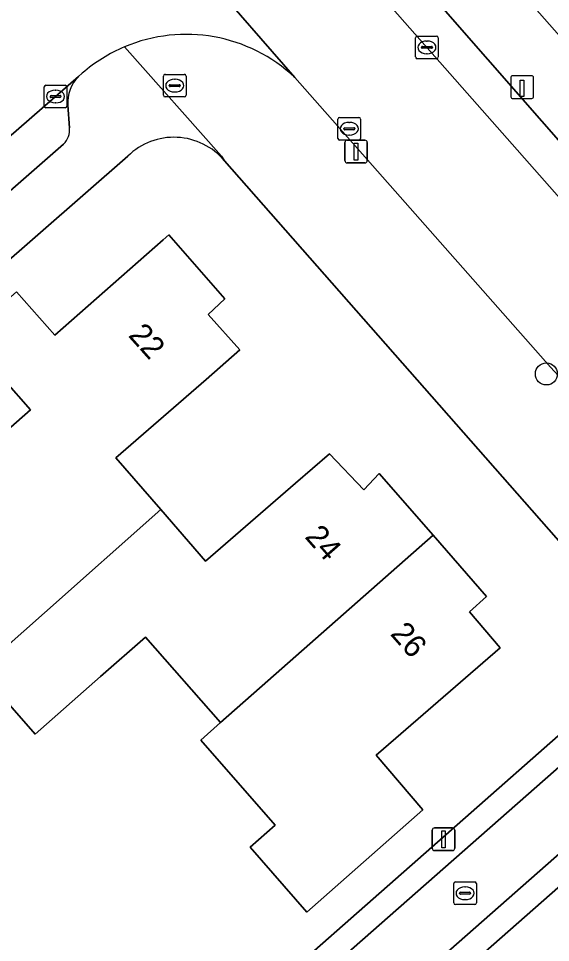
# Model space of a CAD drawing. Extents: x 157320 to 158835, y 386650 to 388491.
# Drawn here: x 157647.93 to 157671.43, y 387796.62 to 387837.43 of the extents above; entities that cross this region are included whole.
import ezdxf

# ---------------------------------------------------------------- set-up
doc = ezdxf.new("R2010")
doc.units = 0
for name, color, linetype in [('IMGEO_Boom', 7, 'Continuous'), ('IMGEO_Brandkraan', 7, 'Continuous'), ('IMGEO_Erf', 7, 'Continuous'), ('IMGEO_Kolk', 7, 'Continuous'), ('IMGEO_Laadpaal', 7, 'Continuous'), ('IMGEO_Lichtmast', 7, 'Continuous'), ('IMGEO_Muur', 7, 'Continuous'), ('IMGEO_Pand', 7, 'Continuous'), ('IMGEO_Pand_nummerreeks', 7, 'Continuous'), ('IMGEO_Parkeervlak_open', 7, 'Continuous'), ('IMGEO_Rijbaan_lokaal_open', 7, 'Continuous'), ('IMGEO_Voetpad_open', 7, 'Continuous')]:
    doc.layers.add(name, color=color, linetype=linetype)

msp = doc.modelspace()

# ---------------------------------------------------------------- linework, layer by layer
at = {"layer": 'IMGEO_Boom'}
msp.add_circle((157671.251, 387821.734), 0.489, dxfattribs=at)
at = {"layer": 'IMGEO_Brandkraan'}
for p, q in [((157654.334, 387834.039), (157654.334, 387834.891)), ((157654.409, 387834.965), (157655.261, 387834.965)), ((157654.822, 387834.745), (157654.847, 387834.745)), ((157655.335, 387834.891), (157655.335, 387834.039)), ((157654.593, 387834.459), (157654.593, 387834.471)), ((157655.031, 387834.422), (157654.633, 387834.422)), ((157654.636, 387834.508), (157655.034, 387834.508)), ((157655.077, 387834.471), (157655.077, 387834.459)), ((157655.261, 387833.965), (157654.409, 387833.965)), ((157654.845, 387834.185), (157654.82, 387834.185))]:
    msp.add_line(p, q, dxfattribs=at)
for points in [[(157654.334, 387834.039), (157654.334, 387834.891)], [(157654.409, 387834.965), (157655.261, 387834.965)], [(157655.335, 387834.891), (157655.335, 387834.039)], [(157655.261, 387833.965), (157654.409, 387833.965)]]:
    msp.add_lwpolyline(points, dxfattribs=at)
for centre, radius, start, end in [((157654.411, 387834.889), 0.0765, 91.552, 178.448), ((157654.411, 387834.889), 0.0765, 91.552, 178.448), ((157655.259, 387834.889), 0.0765, 1.552, 88.448), ((157655.259, 387834.889), 0.0765, 1.552, 88.448), ((157654.633, 387834.468), 0.0403, 85.8775, 175.7526), ((157654.63, 387834.458), 0.0366, 178.938, 274.7102), ((157655.034, 387834.465), 0.043, 264.8664, 352.4533), ((157655.038, 387834.47), 0.0386, 1.7309, 96.639), ((157654.411, 387834.041), 0.0765, 181.552, 268.448), ((157654.411, 387834.041), 0.0765, 181.552, 268.448), ((157655.259, 387834.041), 0.0765, 271.552, 358.448), ((157655.259, 387834.041), 0.0765, 271.552, 358.448)]:
    msp.add_arc(centre, radius, start, end, dxfattribs=at)
for centre, major_axis, ratio, start_param, end_param in [((157654.821, 387834.465), (-0.387, 0.002), 0.722429, 4.712389, 7.853982), ((157654.846, 387834.465), (-0.39, 0.002), 0.717154, 1.570796, 4.712389)]:
    msp.add_ellipse(centre, major_axis=major_axis, ratio=ratio, start_param=start_param, end_param=end_param, dxfattribs=at)
at = {"layer": 'IMGEO_Erf'}
for points in [[(157611.28, 387905.251), (157676.491, 387831.375), (157676.979, 387830.83), (157677.515, 387830.331), (157678.092, 387829.881), (157678.708, 387829.485), (157679.356, 387829.145), (157680.033, 387828.865), (157680.731, 387828.646), (157681.446, 387828.491), (157682.173, 387828.4), (157682.904, 387828.374), (157683.635, 387828.414), (157684.359, 387828.519), (157684.789, 387828.613), (157729.457, 387839.094), (157721.261, 387874.483)], [(157652.762, 387831.358), (157646.906, 387826.236), (157630.79, 387812.141), (157631.345, 387811.51), (157633.511, 387813.414), (157635.08, 387811.629), (157632.915, 387809.725), (157637.888, 387804.07), (157635.493, 387801.964), (157628.395, 387810.035), (157617.003, 387800.065), (157607.442, 387791.699)], [(157674.457, 387811.128), (157674.052, 387811.797), (157657.033, 387831.146)], [(157647.848, 387825.356), (157649.533, 387823.44), (157654.324, 387827.656), (157654.571, 387827.873), (157657.051, 387825.051), (157656.306, 387824.359), (157657.71, 387822.791), (157656.215, 387821.493), (157652.227, 387818.03), (157654.216, 387815.74), (157656.197, 387813.459), (157660.171, 387816.909), (157661.666, 387818.207), (157663.182, 387816.62), (157663.86, 387817.336), (157666.242, 387814.61), (157668.61, 387811.9), (157667.854, 387811.224), (157669.212, 387809.637), (157667.682, 387808.313), (157664.606, 387805.65), (157663.725, 387804.887), (157665.79, 387802.474), (157660.67, 387797.962), (157658.159, 387800.823), (157659.275, 387801.802), (157655.982, 387805.556), (157656.857, 387806.329), (157653.545, 387810.104), (157651.561, 387808.362), (157648.667, 387805.82), (157646.197, 387808.634)], [(157732.841, 387824.842), (157689.538, 387814.686), (157654.452, 387783.817), (157657.034, 387778.861), (157661.114, 387762.545), (157664.445, 387758.077), (157662.927, 387756.946), (157668.103, 387750), (157672.52, 387744.072), (157667.404, 387740.347), (157668.545, 387738.825), (157675.463, 387729.915), (157675.349, 387729.779), (157690.547, 387709.406)], [(157644.367, 387816.559), (157648.46, 387820.15), (157647.298, 387821.475)], [(157665.567, 387800.286), (157674.127, 387807.828), (157674.136, 387807.943)], [(157650.531, 387787.038), (157665.567, 387800.286)]]:
    msp.add_lwpolyline(points, dxfattribs=at)
msp.add_arc((157654.799, 387829.268), 2.918, 40.0468, 134.2699, dxfattribs=at)
at = {"layer": 'IMGEO_Kolk'}
for p, q in [((157665.471, 387835.731), (157665.471, 387836.583)), ((157665.546, 387836.657), (157666.398, 387836.657)), ((157665.959, 387836.437), (157665.984, 387836.437)), ((157666.472, 387836.583), (157666.472, 387835.731)), ((157665.73, 387836.151), (157665.73, 387836.163)), ((157666.168, 387836.114), (157665.77, 387836.114)), ((157665.773, 387836.2), (157666.171, 387836.2)), ((157666.214, 387836.163), (157666.214, 387836.151)), ((157666.398, 387835.657), (157665.546, 387835.657)), ((157665.982, 387835.877), (157665.957, 387835.877)), ((157649.068, 387833.56), (157649.068, 387834.412)), ((157649.143, 387834.486), (157649.995, 387834.486)), ((157650.069, 387834.412), (157650.069, 387833.56)), ((157649.327, 387833.98), (157649.327, 387833.992)), ((157649.765, 387833.943), (157649.367, 387833.943)), ((157649.37, 387834.029), (157649.768, 387834.029)), ((157649.556, 387834.266), (157649.581, 387834.266)), ((157649.811, 387833.992), (157649.811, 387833.98)), ((157649.995, 387833.486), (157649.143, 387833.486)), ((157649.579, 387833.706), (157649.554, 387833.706)), ((157662.117, 387833.061), (157662.969, 387833.061)), ((157662.042, 387832.135), (157662.042, 387832.987)), ((157662.53, 387832.841), (157662.555, 387832.841)), ((157663.043, 387832.987), (157663.043, 387832.135)), ((157662.301, 387832.555), (157662.301, 387832.567)), ((157662.739, 387832.518), (157662.341, 387832.518)), ((157662.344, 387832.604), (157662.742, 387832.604)), ((157662.553, 387832.281), (157662.528, 387832.281)), ((157662.785, 387832.567), (157662.785, 387832.555)), ((157662.969, 387832.061), (157662.117, 387832.061)), ((157667.157, 387798.369), (157667.157, 387799.221)), ((157667.232, 387799.295), (157668.084, 387799.295)), ((157668.158, 387799.221), (157668.158, 387798.369)), ((157667.416, 387798.789), (157667.416, 387798.801)), ((157667.459, 387798.838), (157667.857, 387798.838)), ((157667.645, 387799.075), (157667.67, 387799.075)), ((157667.9, 387798.801), (157667.9, 387798.789)), ((157667.854, 387798.752), (157667.456, 387798.752)), ((157667.668, 387798.515), (157667.643, 387798.515)), ((157668.084, 387798.295), (157667.232, 387798.295))]:
    msp.add_line(p, q, dxfattribs=at)
for points in [[(157665.471, 387835.731), (157665.471, 387836.583)], [(157665.546, 387836.657), (157666.398, 387836.657)], [(157666.472, 387836.583), (157666.472, 387835.731)], [(157666.398, 387835.657), (157665.546, 387835.657)], [(157649.068, 387833.56), (157649.068, 387834.412)], [(157649.143, 387834.486), (157649.995, 387834.486)], [(157650.069, 387834.412), (157650.069, 387833.56)], [(157649.995, 387833.486), (157649.143, 387833.486)], [(157662.117, 387833.061), (157662.969, 387833.061)], [(157662.042, 387832.135), (157662.042, 387832.987)], [(157663.043, 387832.987), (157663.043, 387832.135)], [(157662.969, 387832.061), (157662.117, 387832.061)], [(157667.157, 387798.369), (157667.157, 387799.221)], [(157667.232, 387799.295), (157668.084, 387799.295)], [(157668.158, 387799.221), (157668.158, 387798.369)], [(157668.084, 387798.295), (157667.232, 387798.295)]]:
    msp.add_lwpolyline(points, dxfattribs=at)
for centre, radius, start, end in [((157665.548, 387836.581), 0.0765, 91.552, 178.448), ((157665.548, 387836.581), 0.0765, 91.552, 178.448), ((157666.396, 387836.581), 0.0765, 1.552, 88.448), ((157666.396, 387836.581), 0.0765, 1.552, 88.448), ((157665.77, 387836.16), 0.0403, 85.8775, 175.7526), ((157665.767, 387836.15), 0.0366, 178.938, 274.7102), ((157666.171, 387836.157), 0.043, 264.8664, 352.4533), ((157666.175, 387836.162), 0.0386, 1.7309, 96.639), ((157665.548, 387835.733), 0.0765, 181.552, 268.448), ((157665.548, 387835.733), 0.0765, 181.552, 268.448), ((157666.396, 387835.733), 0.0765, 271.552, 358.448), ((157666.396, 387835.733), 0.0765, 271.552, 358.448), ((157649.145, 387834.41), 0.0765, 91.552, 178.448), ((157649.145, 387834.41), 0.0765, 91.552, 178.448), ((157649.993, 387834.41), 0.0765, 1.552, 88.448), ((157649.993, 387834.41), 0.0765, 1.552, 88.448), ((157649.367, 387833.989), 0.0403, 85.8775, 175.7526), ((157649.364, 387833.979), 0.0366, 178.938, 274.7102), ((157649.768, 387833.986), 0.043, 264.8664, 352.4533), ((157649.772, 387833.991), 0.0386, 1.7309, 96.639), ((157649.145, 387833.562), 0.0765, 181.552, 268.448), ((157649.145, 387833.562), 0.0765, 181.552, 268.448), ((157649.993, 387833.562), 0.0765, 271.552, 358.448), ((157649.993, 387833.562), 0.0765, 271.552, 358.448), ((157662.119, 387832.985), 0.0765, 91.552, 178.448), ((157662.119, 387832.985), 0.0765, 91.552, 178.448), ((157662.967, 387832.985), 0.0765, 1.552, 88.448), ((157662.967, 387832.985), 0.0765, 1.552, 88.448), ((157662.341, 387832.564), 0.0403, 85.8775, 175.7526), ((157662.338, 387832.554), 0.0366, 178.938, 274.7102), ((157662.742, 387832.561), 0.043, 264.8664, 352.4533), ((157662.746, 387832.566), 0.0386, 1.7309, 96.639), ((157662.119, 387832.137), 0.0765, 181.552, 268.448), ((157662.119, 387832.137), 0.0765, 181.552, 268.448), ((157662.967, 387832.137), 0.0765, 271.552, 358.448), ((157662.967, 387832.137), 0.0765, 271.552, 358.448), ((157667.234, 387799.219), 0.0765, 91.552, 178.448), ((157667.234, 387799.219), 0.0765, 91.552, 178.448), ((157668.082, 387799.219), 0.0765, 1.552, 88.448), ((157668.082, 387799.219), 0.0765, 1.552, 88.448), ((157667.456, 387798.798), 0.0403, 85.8775, 175.7526), ((157667.453, 387798.788), 0.0366, 178.938, 274.7102), ((157667.857, 387798.795), 0.043, 264.8664, 352.4533), ((157667.861, 387798.8), 0.0386, 1.7309, 96.639), ((157667.234, 387798.371), 0.0765, 181.552, 268.448), ((157667.234, 387798.371), 0.0765, 181.552, 268.448), ((157668.082, 387798.371), 0.0765, 271.552, 358.448), ((157668.082, 387798.371), 0.0765, 271.552, 358.448)]:
    msp.add_arc(centre, radius, start, end, dxfattribs=at)
for centre, major_axis, ratio, start_param, end_param in [((157665.958, 387836.157), (-0.387, 0.002), 0.722429, 4.712389, 7.853982), ((157665.983, 387836.157), (-0.39, 0.002), 0.717154, 1.570796, 4.712389), ((157649.555, 387833.986), (-0.387, 0.002), 0.722429, 4.712389, 7.853982), ((157649.58, 387833.986), (-0.39, 0.002), 0.717154, 1.570796, 4.712389), ((157662.529, 387832.561), (-0.387, 0.002), 0.722429, 4.712389, 7.853982), ((157662.554, 387832.561), (-0.39, 0.002), 0.717154, 1.570796, 4.712389), ((157667.644, 387798.795), (-0.387, 0.002), 0.722429, 4.712389, 7.853982), ((157667.669, 387798.795), (-0.39, 0.002), 0.717154, 1.570796, 4.712389)]:
    msp.add_ellipse(centre, major_axis=major_axis, ratio=ratio, start_param=start_param, end_param=end_param, dxfattribs=at)
at = {"layer": 'IMGEO_Laadpaal'}
for p, q in [((157669.68, 387834.816), (157669.68, 387833.975)), ((157669.68, 387834.816), (157669.68, 387833.975)), ((157670.596, 387834.9), (157669.755, 387834.9)), ((157670.596, 387834.9), (157669.755, 387834.9)), ((157670.68, 387833.984), (157670.68, 387834.825)), ((157670.68, 387833.984), (157670.68, 387834.825)), ((157669.764, 387833.9), (157670.605, 387833.9)), ((157669.764, 387833.9), (157670.605, 387833.9))]:
    msp.add_line(p, q, dxfattribs=at)
msp.add_lwpolyline([(157670.095, 387834.713), (157670.255, 387834.713), (157670.255, 387833.98), (157670.095, 387833.98), (157670.095, 387834.713)], dxfattribs=at)
for centre, start, end in [((157669.758, 387834.822), 92.4484, 184.2845), ((157669.758, 387834.822), 92.4484, 184.2845), ((157670.602, 387834.822), 2.4484, 94.2845), ((157670.602, 387834.822), 2.4484, 94.2845), ((157669.758, 387833.978), 182.4484, 274.2845), ((157669.758, 387833.978), 182.4484, 274.2845), ((157670.602, 387833.978), 272.4484, 4.2845), ((157670.602, 387833.978), 272.4484, 4.2845)]:
    msp.add_arc(centre, 0.0779, start, end, dxfattribs=at)
at = {"layer": 'IMGEO_Lichtmast'}
for p, q in [((157662.346, 387831.155), (157662.346, 387831.955)), ((157662.346, 387831.955), (157662.346, 387831.155)), ((157662.446, 387832.055), (157663.236, 387832.055)), ((157663.236, 387832.055), (157662.446, 387832.055)), ((157663.336, 387831.955), (157663.336, 387831.155)), ((157663.336, 387831.155), (157663.336, 387831.955)), ((157663.236, 387831.055), (157662.446, 387831.055)), ((157662.446, 387831.055), (157663.236, 387831.055)), ((157666.311, 387801.682), (157667.101, 387801.682)), ((157667.101, 387801.682), (157666.311, 387801.682)), ((157666.211, 387800.782), (157666.211, 387801.582)), ((157666.211, 387801.582), (157666.211, 387800.782)), ((157667.201, 387801.582), (157667.201, 387800.782)), ((157667.201, 387800.782), (157667.201, 387801.582)), ((157667.101, 387800.682), (157666.311, 387800.682)), ((157666.311, 387800.682), (157667.101, 387800.682))]:
    msp.add_line(p, q, dxfattribs=at)
for points in [[(157662.766, 387831.93), (157662.916, 387831.93), (157662.916, 387831.18), (157662.766, 387831.18), (157662.766, 387831.93)], [(157666.631, 387801.557), (157666.781, 387801.557), (157666.781, 387800.807), (157666.631, 387800.807), (157666.631, 387801.557)]]:
    msp.add_lwpolyline(points, dxfattribs=at)
for centre, start, end in [((157662.446, 387831.955), 90, 180), ((157662.446, 387831.955), 90, 180), ((157663.236, 387831.955), 0, 90), ((157663.236, 387831.955), 360, 90), ((157662.446, 387831.155), 180, 270), ((157662.446, 387831.155), 180, 270), ((157663.236, 387831.155), 270, 0), ((157663.236, 387831.155), 270, 0), ((157666.311, 387801.582), 90, 180), ((157666.311, 387801.582), 90, 180), ((157667.101, 387801.582), 0, 90), ((157667.101, 387801.582), 360, 90), ((157666.311, 387800.782), 180, 270), ((157666.311, 387800.782), 180, 270), ((157667.101, 387800.782), 270, 0), ((157667.101, 387800.782), 270, 0)]:
    msp.add_arc(centre, 0.1, start, end, dxfattribs=at)
at = {"layer": 'IMGEO_Muur'}
msp.add_lwpolyline([(157651.028, 387786.092), (157650.531, 387787.038), (157665.567, 387800.286)], dxfattribs=at)
at = {"layer": 'IMGEO_Pand'}
for points in [[(157656.215, 387821.493), (157657.71, 387822.791), (157656.306, 387824.359), (157657.051, 387825.051), (157654.571, 387827.873), (157654.324, 387827.656), (157649.533, 387823.44), (157647.848, 387825.356), (157645.616, 387823.393), (157647.298, 387821.475), (157648.46, 387820.15), (157644.367, 387816.559), (157646.611, 387814.001), (157647.004, 387813.553), (157644.869, 387811.68), (157646.321, 387810.026), (157645.561, 387809.359), (157646.197, 387808.634), (157649.086, 387811.182), (157654.216, 387815.74), (157652.227, 387818.03)], [(157666.242, 387814.61), (157663.86, 387817.336), (157663.182, 387816.62), (157661.666, 387818.207), (157660.171, 387816.909), (157656.197, 387813.459), (157654.216, 387815.74), (157649.086, 387811.182), (157646.197, 387808.634), (157648.667, 387805.82), (157651.561, 387808.362), (157653.545, 387810.104), (157656.857, 387806.329), (157658.944, 387808.17)], [(157667.682, 387808.313), (157669.212, 387809.637), (157667.854, 387811.224), (157668.61, 387811.9), (157666.242, 387814.61), (157658.944, 387808.17), (157656.857, 387806.329), (157655.982, 387805.556), (157659.275, 387801.802), (157658.159, 387800.823), (157660.67, 387797.962), (157665.79, 387802.474), (157663.725, 387804.887), (157664.606, 387805.65)]]:
    msp.add_lwpolyline(points, close=True, dxfattribs=at)
at = {"layer": 'IMGEO_Parkeervlak_open'}
for points in [[(157608.833, 387900.938), (157673.92, 387827.143), (157673.883, 387827.191), (157673.8, 387827.312), (157673.729, 387827.44), (157673.669, 387827.574), (157673.621, 387827.713), (157673.586, 387827.856), (157673.564, 387828.001), (157673.555, 387828.147), (157673.559, 387828.294), (157673.628, 387829.414), (157673.63, 387829.523), (157673.622, 387829.632), (157673.605, 387829.739), (157673.578, 387829.845), (157673.542, 387829.947), (157673.496, 387830.047), (157673.442, 387830.141), (157673.38, 387830.231), (157673.331, 387830.291), (157666.378, 387838.229)], [(157650.581, 387834.87), (157636.25, 387822.385), (157620.732, 387808.831), (157609.797, 387799.195), (157607.46, 387797.138), (157606.933, 387796.674)], [(157650.187, 387832.607), (157650.113, 387833.608)], [(157609.821, 387796.834), (157626.632, 387811.526), (157629.469, 387814.006), (157649.925, 387831.883)]]:
    msp.add_lwpolyline(points, dxfattribs=at)
for centre, radius, start, end in [((157651.721, 387833.729), 1.613, 134.9904, 184.316), ((157649.299, 387832.519), 0.892, 314.5481, 5.6637)]:
    msp.add_arc(centre, radius, start, end, dxfattribs=at)
at = {"layer": 'IMGEO_Rijbaan_lokaal_open'}
for points in [[(157729.55, 387834.104), (157728.562, 387833.876), (157724.892, 387833.031), (157714.68, 387830.684), (157683.612, 387823.423), (157683.417, 387823.394), (157683.222, 387823.368), (157682.956, 387823.339), (157682.032, 387823.293), (157681.107, 387823.329), (157680.189, 387823.447), (157679.285, 387823.647), (157678.403, 387823.927), (157677.549, 387824.285), (157676.731, 387824.718), (157675.955, 387825.222), (157675.226, 387825.793), (157674.552, 387826.427), (157673.92, 387827.143), (157608.833, 387900.938)], [(157602.837, 387900.03), (157604.73, 387897.915), (157647.931, 387848.881), (157648.432, 387848.271), (157660.135, 387834.829), (157671.431, 387822.03)], [(157660.135, 387834.829), (157648.432, 387848.271)], [(157646.017, 387837.483), (157632.713, 387825.956), (157617.194, 387812.367), (157606.984, 387803.438), (157604.13, 387800.92), (157607.46, 387797.138), (157609.797, 387799.195), (157620.732, 387808.831), (157636.25, 387822.385), (157650.581, 387834.87)], [(157650.581, 387834.87), (157650.752, 387835.019)], [(157674.136, 387807.943), (157674.127, 387807.828), (157674.005, 387806.306), (157651.028, 387786.092), (157652.411, 387783.461), (157687.304, 387814.165), (157674.457, 387811.128)]]:
    msp.add_lwpolyline(points, dxfattribs=at)
for centre, radius, start, end in [((157655.338, 387829.727), 7.003, 46.7625, 112.8827), ((157655.36, 387829.694), 7.042, 112.944, 130.8731), ((157680.912, 387830.362), 12.622, 221.3083, 258.6211)]:
    msp.add_arc(centre, radius, start, end, dxfattribs=at)
at = {"layer": 'IMGEO_Voetpad_open'}
for points in [[(157676.491, 387831.375), (157611.28, 387905.251)], [(157666.378, 387838.229), (157673.331, 387830.291)], [(157657.033, 387831.146), (157656.894, 387831.355), (157652.615, 387836.179)], [(157652.615, 387836.179), (157656.894, 387831.355), (157657.033, 387831.146), (157674.052, 387811.797), (157674.457, 387811.128), (157687.304, 387814.165), (157689.538, 387814.686), (157732.841, 387824.842), (157731.787, 387829.356)], [(157650.752, 387835.019), (157650.581, 387834.87)], [(157671.431, 387822.03), (157660.135, 387834.829)], [(157650.113, 387833.608), (157650.187, 387832.607)], [(157649.925, 387831.883), (157629.469, 387814.006), (157629.798, 387813.63), (157626.961, 387811.15), (157626.632, 387811.526), (157609.821, 387796.834)], [(157529.707, 387722.081), (157536.727, 387728.304), (157548.792, 387738.997), (157551.146, 387741.084), (157572.416, 387759.957), (157573.25, 387760.707), (157577.053, 387764.23), (157593.698, 387779.343), (157601.499, 387786.426), (157603.416, 387788.161), (157606.621, 387790.971), (157607.442, 387791.699), (157617.003, 387800.065), (157628.395, 387810.035), (157630.79, 387812.141), (157646.906, 387826.236), (157652.762, 387831.358)], [(157689.538, 387814.686), (157687.304, 387814.165), (157652.411, 387783.461), (157652.933, 387782.468), (157655.208, 387778.141), (157658.906, 387762.988), (157659.333, 387761.239), (157653.16, 387758.176), (157649.389, 387756.267), (157650.353, 387754.548), (157650.828, 387753.596), (157650.874, 387753.619), (157651.656, 387754.009)], [(157653.879, 387753.597), (157656.565, 387750), (157657.386, 387748.771), (157662.294, 387742.225), (157664.679, 387743.983), (157660.17, 387750), (157659.244, 387751.236), (157660.706, 387759.926), (157661.114, 387762.545), (157657.034, 387778.861), (157654.452, 387783.817), (157689.538, 387814.686)]]:
    msp.add_lwpolyline(points, dxfattribs=at)
msp.add_lwpolyline([(157650.531, 387787.038), (157651.028, 387786.092), (157674.005, 387806.306), (157674.127, 387807.828), (157665.567, 387800.286)], close=True, dxfattribs=at)
for centre, radius, start, end in [((157655.338, 387829.727), 7.003, 46.7625, 112.8827), ((157655.36, 387829.694), 7.042, 112.944, 130.8731), ((157651.721, 387833.729), 1.613, 134.9904, 184.316), ((157649.299, 387832.519), 0.892, 314.5481, 5.6637), ((157654.799, 387829.268), 2.918, 40.0468, 134.2699), ((157680.912, 387830.362), 12.622, 221.3083, 258.6211)]:
    msp.add_arc(centre, radius, start, end, dxfattribs=at)

# ---------------------------------------------------------------- texts
at = {"layer": 'IMGEO_Pand_nummerreeks'}
for s, rotation, p in [('22', 311.8429, (157652.749, 387823.414)), ('24', 311.3616, (157660.545, 387814.517)), ('26', 311.3616, (157664.318, 387810.232))]:
    msp.add_text(s, height=1, rotation=rotation, dxfattribs=at).set_placement(p)

doc.saveas('drawing.dxf')
